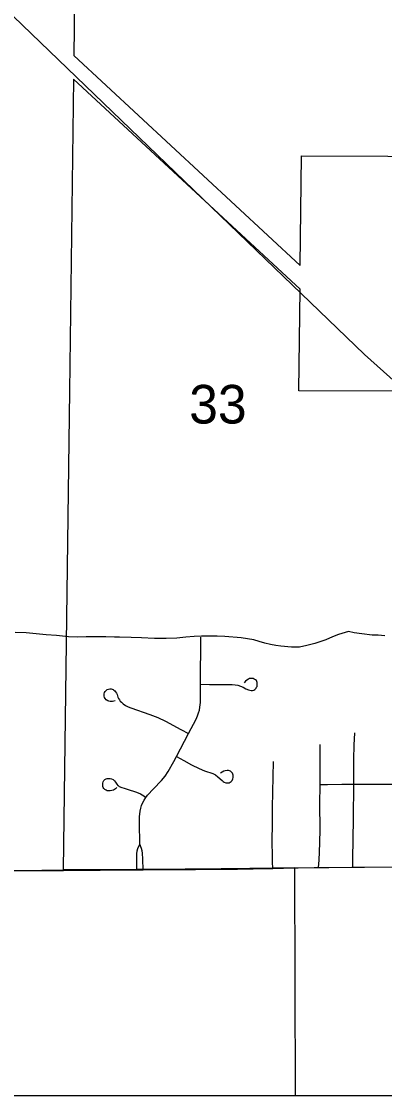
# Model space of a CAD drawing. Extents: x 0 to 34, y 0 to 22.
# Drawn here: x 6.808 to 7.201, y 14.1 to 15.265 of the extents above; entities that cross this region are included whole.
import ezdxf

# ---------------------------------------------------------------- set-up
doc = ezdxf.new("R2010")
doc.units = 0
for name, color, linetype in [('Default', 7, 'Continuous'), ('GM_X_City_Street', 7, 'Continuous'), ('GM_X_Interstate_Route', 7, 'Continuous'), ('GM_X_Minor_River', 7, 'Continuous'), ('GM_X_Rail_Line', 7, 'Continuous'), ('GM_X_Section', 7, 'Continuous'), ('GM_X_Section_Text', 7, 'Continuous'), ('GM_X_State_Route', 7, 'Continuous')]:
    doc.layers.add(name, color=color, linetype=linetype)

msp = doc.modelspace()

# ---------------------------------------------------------------- linework, layer by layer
at = {"layer": 'Default'}
for points in [[(6.8663, 15.3783), (6.8645, 15.2275), (7.11, 14.9999), (7.1115, 15.1189), (7.3918, 15.1179)], [(7.3899, 14.8635), (7.1083, 14.8639), (7.1097, 14.9744), (6.8642, 15.202), (6.86, 14.8638), (6.8532, 14.3452), (6.9327, 14.3456), (6.9393, 14.3457), (6.9823, 14.3455), (7.1038, 14.3474), (7.1046, 14.1), (7.6375, 14.1)]]:
    msp.add_lwpolyline(points, dxfattribs=at)
msp.add_lwpolyline([(6.5976, 14.1), (7.6078, 14.1), (7.6069, 14.3511), (6.5967, 14.3417)], close=True, dxfattribs=at)
at = {"layer": 'GM_X_City_Street'}
for points in [[(6.936, 14.3727), (6.9358, 14.3958), (6.9359, 14.4021), (6.9365, 14.4084), (6.9371, 14.4115), (6.938, 14.4146), (6.9393, 14.4176), (6.9408, 14.4204), (6.9426, 14.4231), (6.9445, 14.4256), (6.9509, 14.4326), (6.9596, 14.4415), (6.9635, 14.4463), (6.967, 14.4513), (6.9731, 14.4621), (6.9759, 14.4676), (6.989, 14.4925), (6.9971, 14.508), (6.9986, 14.5117), (6.9998, 14.5151), (7.0007, 14.5178), (7.0012, 14.5209), (7.0017, 14.5236), (7.0018, 14.5263), (7.0019, 14.5309), (7.002, 14.546), (7.0023, 14.5969)], [(7.002, 14.546), (7.0115, 14.5458), (7.0239, 14.5456), (7.0362, 14.5455), (7.0393, 14.5453), (7.0424, 14.5449), (7.0453, 14.5439), (7.0481, 14.5426), (7.0509, 14.5411), (7.0538, 14.5398), (7.0552, 14.5394), (7.0568, 14.5392), (7.0583, 14.5392), (7.0597, 14.5396), (7.0608, 14.5403), (7.0615, 14.541), (7.0621, 14.5417), (7.0627, 14.5427), (7.0632, 14.5436), (7.0634, 14.5448), (7.0634, 14.5462), (7.0632, 14.5478), (7.0629, 14.549), (7.0624, 14.5499), (7.0615, 14.5508), (7.0602, 14.5516), (7.059, 14.552), (7.0574, 14.5523), (7.0561, 14.5522), (7.0551, 14.5521), (7.0538, 14.5516), (7.052, 14.5503), (7.0507, 14.5491), (7.0492, 14.5476)], [(6.9094, 14.5281), (6.908, 14.5275), (6.9067, 14.5271), (6.9054, 14.5271), (6.9039, 14.5272), (6.9026, 14.5274), (6.9014, 14.5279), (6.8998, 14.5291), (6.8987, 14.5303), (6.898, 14.5316), (6.8976, 14.5331), (6.8976, 14.5343), (6.8976, 14.5356), (6.898, 14.537), (6.8985, 14.5382), (6.8995, 14.5392), (6.9007, 14.5401), (6.9022, 14.5407), (6.9037, 14.5409), (6.905, 14.5408), (6.9062, 14.5405), (6.9071, 14.5402), (6.9081, 14.5395), (6.909, 14.5387), (6.9097, 14.5378), (6.9107, 14.5364), (6.9116, 14.5347), (6.9125, 14.532), (6.9132, 14.5304), (6.914, 14.5289), (6.9149, 14.5277), (6.9162, 14.5264), (6.9181, 14.5247), (6.9207, 14.523), (6.9235, 14.5216), (6.9264, 14.5205), (6.9469, 14.5132), (6.9556, 14.5098), (6.9641, 14.5059), (6.9806, 14.497), (6.989, 14.4925)], [(7.1668, 14.3477), (7.167, 14.3562), (7.1677, 14.4001), (7.1679, 14.4375), (7.168, 14.4527), (7.1679, 14.4648), (7.1683, 14.4797), (7.169, 14.4931)], [(7.1299, 14.3474), (7.1305, 14.355), (7.1311, 14.3735), (7.1316, 14.389), (7.1313, 14.4154), (7.1315, 14.4371), (7.1317, 14.4415), (7.1317, 14.4806)], [(6.9759, 14.4676), (6.9838, 14.4632), (6.992, 14.4585), (7.0005, 14.4545), (7.0064, 14.4521), (7.0153, 14.4491), (7.0181, 14.4476), (7.0206, 14.4457), (7.0252, 14.4414), (7.0265, 14.4406), (7.0277, 14.4398), (7.0292, 14.4392), (7.0306, 14.439), (7.0318, 14.439), (7.0328, 14.4392), (7.034, 14.4397), (7.0351, 14.4406), (7.0362, 14.4417), (7.0369, 14.4432), (7.0373, 14.4447), (7.0374, 14.4461), (7.0372, 14.4475), (7.0369, 14.4486), (7.0365, 14.4495), (7.0359, 14.4503), (7.0344, 14.4516), (7.0333, 14.4521), (7.0322, 14.4524), (7.0307, 14.4524), (7.0285, 14.452), (7.0271, 14.4515), (7.0254, 14.4507), (7.0235, 14.4495)], [(7.0798, 14.3892), (7.08, 14.4121), (7.0811, 14.4622)], [(6.9111, 14.434), (6.9099, 14.4326), (6.9088, 14.4318), (6.9075, 14.4312), (6.906, 14.4306), (6.904, 14.4303), (6.9023, 14.4302), (6.9009, 14.4304), (6.8995, 14.431), (6.8981, 14.4318), (6.8972, 14.4329), (6.8966, 14.4339), (6.8961, 14.4349), (6.896, 14.4359), (6.8959, 14.4369), (6.896, 14.4387), (6.8965, 14.4402), (6.8972, 14.4415), (6.8983, 14.4426), (6.8995, 14.4433), (6.9009, 14.4438), (6.9025, 14.4439), (6.904, 14.4437), (6.9056, 14.4432), (6.9071, 14.4425), (6.9086, 14.4411), (6.9098, 14.4396), (6.9113, 14.4374), (6.9123, 14.4362), (6.9131, 14.4357), (6.9139, 14.4352), (6.9168, 14.4341), (6.9193, 14.4332), (6.9224, 14.4322), (6.9326, 14.429), (6.9368, 14.4272), (6.9404, 14.4251), (6.9426, 14.4231)], [(7.1315, 14.4371), (7.1395, 14.4372), (7.155, 14.4374), (7.1679, 14.4375), (7.1828, 14.4376), (7.2256, 14.4377), (7.2408, 14.4379), (7.2972, 14.4386), (7.3144, 14.4387), (7.3723, 14.4393), (7.388, 14.4396), (7.4001, 14.4398), (7.458, 14.4404), (7.4623, 14.4404), (7.4857, 14.4406), (7.5357, 14.4422), (7.6003, 14.4427), (7.6082, 14.4426)], [(7.0801, 14.3463), (7.08, 14.3534), (7.0797, 14.3816), (7.0798, 14.3892)], [(6.9329, 14.3446), (6.933, 14.3574), (6.933, 14.362), (6.9333, 14.3653), (6.9339, 14.3679), (6.936, 14.3727)], [(6.9396, 14.3447), (6.9394, 14.3561), (6.939, 14.3629), (6.9386, 14.3653), (6.9379, 14.368), (6.936, 14.3727)]]:
    msp.add_lwpolyline(points, dxfattribs=at)
at = {"layer": 'GM_X_Interstate_Route'}
msp.add_lwpolyline([(4.7033, 15.2872), (4.704, 15.2372), (4.7044, 15.1626), (4.7047, 15.0849), (4.7047, 15.0383), (4.7052, 14.9668), (4.7054, 14.8953), (4.7055, 14.7399), (4.705, 14.6903), (4.7046, 14.5938), (4.705, 14.4959), (4.7052, 14.4725), (4.7052, 14.4414), (4.7052, 14.3917), (4.705, 14.347), (4.7049, 14.3358), (4.7038, 14.2643), (4.7028, 14.1744), (4.7022, 14.1275), (4.7021, 14.1056), (4.7021, 14.1), (8.9, 14.1), (8.9, 17.3895)], dxfattribs=at)
at = {"layer": 'GM_X_Minor_River'}
for points in [[(7.2017, 14.5984), (7.1945, 14.5992), (7.188, 14.5992), (7.1767, 14.6007), (7.1683, 14.6015), (7.1622, 14.603), (7.1513, 14.6), (7.1448, 14.5973), (7.1376, 14.5939), (7.1259, 14.5901), (7.1171, 14.5879), (7.1092, 14.5863), (7.1005, 14.586), (7.0891, 14.5871), (7.0834, 14.5879), (7.0777, 14.589), (7.0716, 14.5905), (7.0656, 14.5924), (7.0595, 14.594), (7.0459, 14.5963), (7.0284, 14.5978), (7.0201, 14.5982), (7.003, 14.5982), (6.9951, 14.5978), (6.986, 14.5971), (6.9761, 14.5959), (6.9648, 14.5955), (6.9522, 14.5956), (6.9378, 14.5963), (6.9268, 14.5967)], [(6.9268, 14.5967), (6.9143, 14.5971), (6.9087, 14.5971), (6.8992, 14.5975), (6.8779, 14.5975), (6.8681, 14.5971), (6.859, 14.5975), (6.8457, 14.5987), (6.8347, 14.5994), (6.8237, 14.6006), (6.8131, 14.6017), (6.801, 14.6021)]]:
    msp.add_lwpolyline(points, dxfattribs=at)
at = {"layer": 'GM_X_Rail_Line'}
msp.add_lwpolyline([(4.6999, 17.2234), (5.1959, 16.7623), (5.6141, 16.3779), (6.1219, 15.9048), (6.7692, 15.2987), (7.1796, 14.9035), (7.6056, 14.5217)], dxfattribs=at)
at = {"layer": 'GM_X_Section'}
msp.add_lwpolyline([(7.6191, 15.3755), (7.6069, 14.3511), (6.5967, 14.3417), (6.6049, 15.379)], close=True, dxfattribs=at)
at = {"layer": 'GM_X_State_Route'}
for points in [[(7.0763, 14.3463), (7.0801, 14.3463), (7.1038, 14.3468), (7.1057, 14.3468)], [(7.1057, 14.3468), (7.1077, 14.3468), (7.1252, 14.3473), (7.1299, 14.3474), (7.1657, 14.3477), (7.1668, 14.3477), (7.2124, 14.3478), (7.2403, 14.3481), (7.2436, 14.3481), (7.2934, 14.3482), (7.3138, 14.3484), (7.3307, 14.3486), (7.3795, 14.349), (7.3878, 14.349), (7.4041, 14.3491), (7.4446, 14.3494), (7.461, 14.3495), (7.5344, 14.3501), (7.5757, 14.3504), (7.5977, 14.3503), (7.6077, 14.3506)], [(6.6732, 14.3435), (6.8535, 14.3441)], [(6.8535, 14.3441), (6.9329, 14.3446), (6.9396, 14.3447), (6.9755, 14.3449)], [(6.9755, 14.3449), (6.9774, 14.3449), (6.9825, 14.345), (6.9966, 14.3451), (7.042, 14.3455), (7.0763, 14.3463)]]:
    msp.add_lwpolyline(points, dxfattribs=at)

# ---------------------------------------------------------------- texts
at = {"layer": 'GM_X_Section_Text'}
msp.add_text('33', height=0.04186, rotation=0, dxfattribs=at).set_placement((6.9896, 14.8286))

doc.saveas('drawing.dxf')
